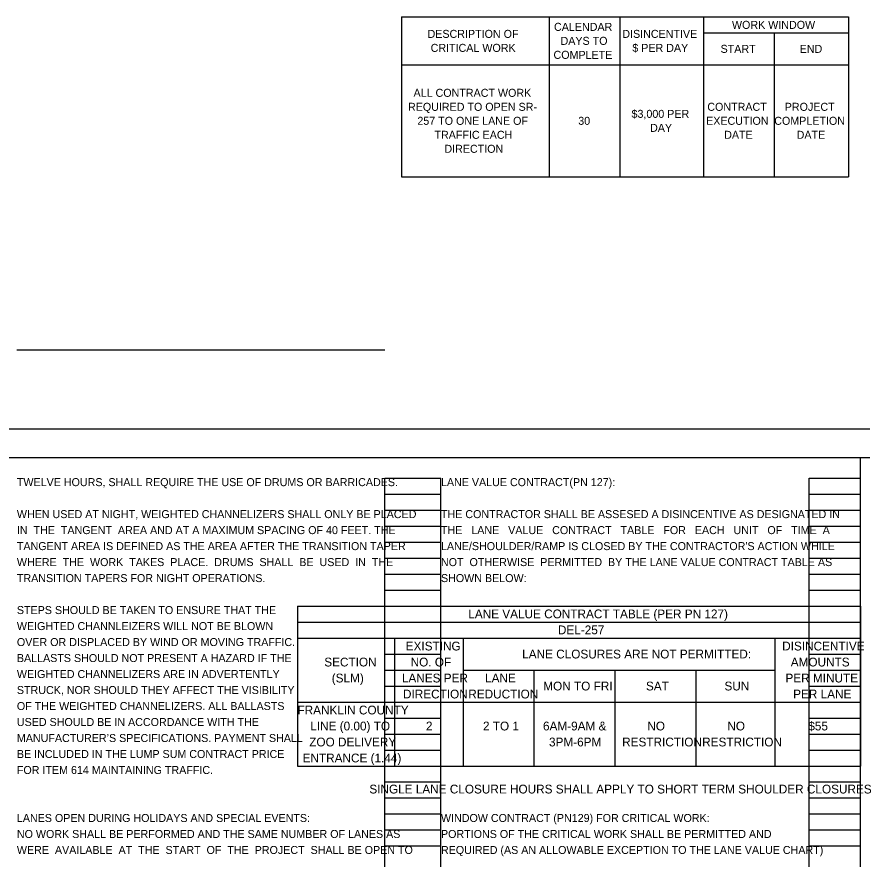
# Model space of a CAD drawing. Extents: x -15.6 to 56.6, y 0 to 56.8.
# Drawn here: x 17.24 to 32.03, y 14.47 to 29.22 of the extents above; entities that cross this region are included whole.
import ezdxf

# ---------------------------------------------------------------- set-up
doc = ezdxf.new("R2010")
doc.units = 0
for name, color, linetype in [('SH_Border', 7, 'Continuous'), ('SH_Cut_Line', 7, 'Continuous'), ('SH_Data', 7, 'Continuous'), ('SH_Text', 7, 'Continuous')]:
    doc.layers.add(name, color=color, linetype=linetype)

msp = doc.modelspace()

# ---------------------------------------------------------------- linework, layer by layer
at = {"layer": 'SH_Border'}
msp.add_line((32, 0.5), (32, 21.5), dxfattribs=at)
msp.add_lwpolyline([(1.5, 21.5), (33.5, 21.5), (33.5, 0.5), (1.5, 0.5)], close=True, dxfattribs=at)
at = {"layer": 'SH_Cut_Line'}
msp.add_lwpolyline([(0, 0), (34, 0), (34, 22), (0, 22)], close=True, dxfattribs=at)
at = {"layer": 'SH_Data'}
for p, q in [((23.68, 0.98), (23.68, 21.14)), ((23.68, 21.14), (24.66, 21.14)), ((24.66, 0.98), (24.66, 21.14)), ((31.1, 0.98), (31.1, 21.14)), ((31.1, 21.14), (32, 21.14)), ((32, 0.98), (32, 21.14)), ((23.68, 20.86), (24.66, 20.86)), ((31.1, 20.86), (32, 20.86)), ((23.68, 20.58), (24.66, 20.58)), ((31.1, 20.58), (32, 20.58)), ((23.68, 20.3), (24.66, 20.3)), ((31.1, 20.3), (32, 20.3)), ((23.68, 20.02), (24.66, 20.02)), ((31.1, 20.02), (32, 20.02)), ((23.68, 19.74), (24.66, 19.74)), ((31.1, 19.74), (32, 19.74)), ((23.68, 19.46), (24.66, 19.46)), ((31.1, 19.46), (32, 19.46)), ((23.68, 19.18), (24.66, 19.18)), ((31.1, 19.18), (32, 19.18)), ((22.151, 18.9), (32, 18.9)), ((22.151, 18.9), (22.151, 16.1)), ((23.68, 18.9), (24.66, 18.9)), ((31.1, 18.9), (32, 18.9)), ((32, 18.9), (32, 16.1)), ((22.151, 18.62), (32, 18.62)), ((23.68, 18.62), (24.66, 18.62)), ((31.1, 18.62), (32, 18.62)), ((22.151, 18.34), (32, 18.34)), ((23.68, 18.34), (24.66, 18.34)), ((23.847, 18.34), (23.847, 16.1)), ((25.049, 18.34), (25.049, 16.1)), ((30.501, 18.34), (30.501, 16.1)), ((31.1, 18.34), (32, 18.34)), ((23.68, 18.06), (24.66, 18.06)), ((31.1, 18.06), (32, 18.06)), ((23.68, 17.78), (24.66, 17.78)), ((25.049, 17.78), (30.501, 17.78)), ((26.285, 17.78), (26.285, 16.1)), ((27.701, 17.78), (27.701, 16.1)), ((29.118, 17.78), (29.118, 16.1)), ((31.1, 17.78), (32, 17.78)), ((23.68, 17.5), (24.66, 17.5)), ((31.1, 17.5), (32, 17.5)), ((22.151, 17.22), (32, 17.22)), ((23.68, 17.22), (24.66, 17.22)), ((31.1, 17.22), (32, 17.22)), ((23.68, 16.94), (24.66, 16.94)), ((31.1, 16.94), (32, 16.94)), ((23.68, 16.66), (24.66, 16.66)), ((31.1, 16.66), (32, 16.66)), ((23.68, 16.38), (24.66, 16.38)), ((31.1, 16.38), (32, 16.38)), ((22.151, 16.1), (32, 16.1)), ((23.68, 16.1), (24.66, 16.1)), ((31.1, 16.1), (32, 16.1)), ((23.68, 15.82), (24.66, 15.82)), ((31.1, 15.82), (32, 15.82)), ((23.68, 15.54), (24.66, 15.54)), ((31.1, 15.54), (32, 15.54)), ((23.68, 15.26), (24.66, 15.26)), ((31.1, 15.26), (32, 15.26)), ((23.68, 14.98), (24.66, 14.98)), ((31.1, 14.98), (32, 14.98)), ((23.68, 14.7), (24.66, 14.7)), ((31.1, 14.7), (32, 14.7))]:
    msp.add_line(p, q, dxfattribs=at)
at = {"layer": 'SH_Text'}
for p, q in [((23.968, 29.216), (31.792, 29.216)), ((23.968, 29.216), (23.968, 26.416)), ((26.554, 29.216), (26.554, 26.416)), ((27.789, 29.216), (27.789, 26.416)), ((29.255, 29.216), (29.255, 26.416)), ((31.792, 29.216), (31.792, 26.416)), ((29.255, 28.936), (31.792, 28.936)), ((30.491, 28.936), (30.491, 26.416)), ((23.968, 28.376), (31.792, 28.376)), ((23.968, 26.416), (31.792, 26.416)), ((17.24, 23.384), (23.68, 23.384))]:
    msp.add_line(p, q, dxfattribs=at)

# ---------------------------------------------------------------- texts
at = {"layer": 'SH_Data'}
for s, p in [('LANE VALUE CONTRACT TABLE (PER PN 127)', (25.138, 18.686)), ('DEL-257', (26.706, 18.406)), ('EXISTING', (24.043, 18.123)), ('DISINCENTIVE', (30.63, 18.123)), ('LANE CLOSURES ARE NOT PERMITTED:', (26.081, 17.983)), ('SECTION', (22.618, 17.843)), ('NO. OF', (24.129, 17.843)), ('AMOUNTS', (30.78, 17.843)), ('(SLM)', (22.749, 17.563)), ('LANES PER', (23.976, 17.563)), ('LANE', (25.432, 17.563)), ('PER MINUTE', (30.687, 17.563)), ('MON TO FRI', (26.45, 17.423)), ('SAT', (28.246, 17.423)), ('SUN', (29.62, 17.423)), (' DIRECTION', (23.938, 17.283)), ('REDUCTION', (25.138, 17.283)), ('PER LANE', (30.822, 17.283)), ('FRANKLIN COUNTY', (22.149, 17.003)), ('LINE (0.00) TO', (22.373, 16.723)), ('2', (24.396, 16.723)), ('2 TO 1', (25.395, 16.723)), ('6AM-9AM &', (26.445, 16.723)), ('NO', (28.27, 16.723)), ('NO', (29.67, 16.723)), ('$55', (31.087, 16.723)), ('ZOO DELIVERY', (22.355, 16.443)), ('3PM-6PM', (26.55, 16.443)), ('RESTRICTION', (27.83, 16.443)), ('RESTRICTION', (29.23, 16.443)), ('ENTRANCE (1.44)', (22.239, 16.163)), ('SINGLE LANE CLOSURE HOURS SHALL APPLY TO SHORT TERM SHOULDER CLOSURES', (23.407, 15.619))]:
    msp.add_text(s, height=0.154, dxfattribs=at).set_placement(p)
at = {"layer": 'SH_Text'}
for s, p in [('WORK WINDOW', (29.751, 29.006)), ('DESCRIPTION OF ', (24.425, 28.848)), ('CALENDAR ', (26.638, 28.971)), ('DISINCENTIVE ', (27.833, 28.848)), ('DAYS TO ', (26.752, 28.726)), ('CRITICAL WORK', (24.479, 28.603)), ('$ PER DAY', (28.008, 28.603)), ('START', (29.552, 28.586)), ('END', (30.936, 28.586)), ('COMPLETE', (26.629, 28.481)), ('ALL CONTRACT WORK ', (24.18, 27.816)), ('REQUIRED TO OPEN SR-', (24.083, 27.571)), ('CONTRACT ', (29.32, 27.571)), ('PROJECT ', (30.675, 27.571)), ('$3,000 PER ', (27.994, 27.448)), ('257 TO ONE LANE OF ', (24.247, 27.326)), ('30', (27.062, 27.326)), ('EXECUTION ', (29.299, 27.326)), ('COMPLETION ', (30.491, 27.326)), ('TRAFFIC EACH ', (24.546, 27.081)), ('DAY', (28.318, 27.203)), ('DATE', (29.615, 27.081)), ('DATE', (30.883, 27.081)), ('DIRECTION', (24.72, 26.836)), ('LANE VALUE CONTRACT(PN 127):', (24.66, 21)), ('TWELVE HOURS, SHALL REQUIRE THE USE OF DRUMS OR BARRICADES.', (17.24, 21)), ('WHEN USED AT NIGHT, WEIGHTED CHANNELIZERS SHALL ONLY BE PLACED', (17.24, 20.44)), ('THE CONTRACTOR SHALL BE ASSESED A DISINCENTIVE AS DESIGNATED IN', (24.66, 20.44)), ('IN  THE  TANGENT  AREA AND AT A MAXIMUM SPACING OF 40 FEET. THE', (17.24, 20.16)), ('THE   LANE   VALUE   CONTRACT   TABLE   FOR   EACH   UNIT   OF   TIME  A', (24.66, 20.16)), ('TANGENT AREA IS DEFINED AS THE AREA AFTER THE TRANSITION TAPER', (17.24, 19.88)), ("LANE/SHOULDER/RAMP IS CLOSED BY THE CONTRACTOR'S ACTION WHILE", (24.66, 19.88)), ('WHERE  THE  WORK  TAKES  PLACE.  DRUMS  SHALL  BE  USED  IN  THE', (17.24, 19.6)), ('NOT  OTHERWISE  PERMITTED  BY THE LANE VALUE CONTRACT TABLE AS', (24.66, 19.6)), ('TRANSITION TAPERS FOR NIGHT OPERATIONS.', (17.24, 19.32)), ('SHOWN BELOW:', (24.66, 19.32)), ('STEPS SHOULD BE TAKEN TO ENSURE THAT THE ', (17.24, 18.76)), ('WEIGHTED CHANNLEIZERS WILL NOT BE BLOWN', (17.24, 18.48)), ('OVER OR DISPLACED BY WIND OR MOVING TRAFFIC.', (17.24, 18.2)), ('BALLASTS SHOULD NOT PRESENT A HAZARD IF THE', (17.24, 17.92)), ('WEIGHTED CHANNELIZERS ARE IN ADVERTENTLY', (17.24, 17.64)), ('STRUCK, NOR SHOULD THEY AFFECT THE VISIBILITY', (17.24, 17.36)), ('OF THE WEIGHTED CHANNELIZERS. ALL BALLASTS', (17.24, 17.08)), ('USED SHOULD BE IN ACCORDANCE WITH THE ', (17.24, 16.8)), ('MANUFACTURER’S SPECIFICATIONS. PAYMENT SHALL', (17.24, 16.52)), ('BE INCLUDED IN THE LUMP SUM CONTRACT PRICE', (17.24, 16.24)), ('FOR ITEM 614 MAINTAINING TRAFFIC.', (17.24, 15.96)), ('LANES OPEN DURING HOLIDAYS AND SPECIAL EVENTS:', (17.24, 15.12)), ('WINDOW CONTRACT (PN129) FOR CRITICAL WORK:', (24.66, 15.12)), ('NO WORK SHALL BE PERFORMED AND THE SAME NUMBER OF LANES AS', (17.24, 14.84)), ('PORTIONS OF THE CRITICAL WORK SHALL BE PERMITTED AND ', (24.66, 14.84)), ('WERE  AVAILABLE  AT  THE  START  OF  THE  PROJECT  SHALL BE OPEN TO', (17.24, 14.56)), ('REQUIRED (AS AN ALLOWABLE EXCEPTION TO THE LANE VALUE CHART) ', (24.66, 14.56))]:
    msp.add_text(s, height=0.14, dxfattribs=at).set_placement(p)

doc.saveas('drawing.dxf')
